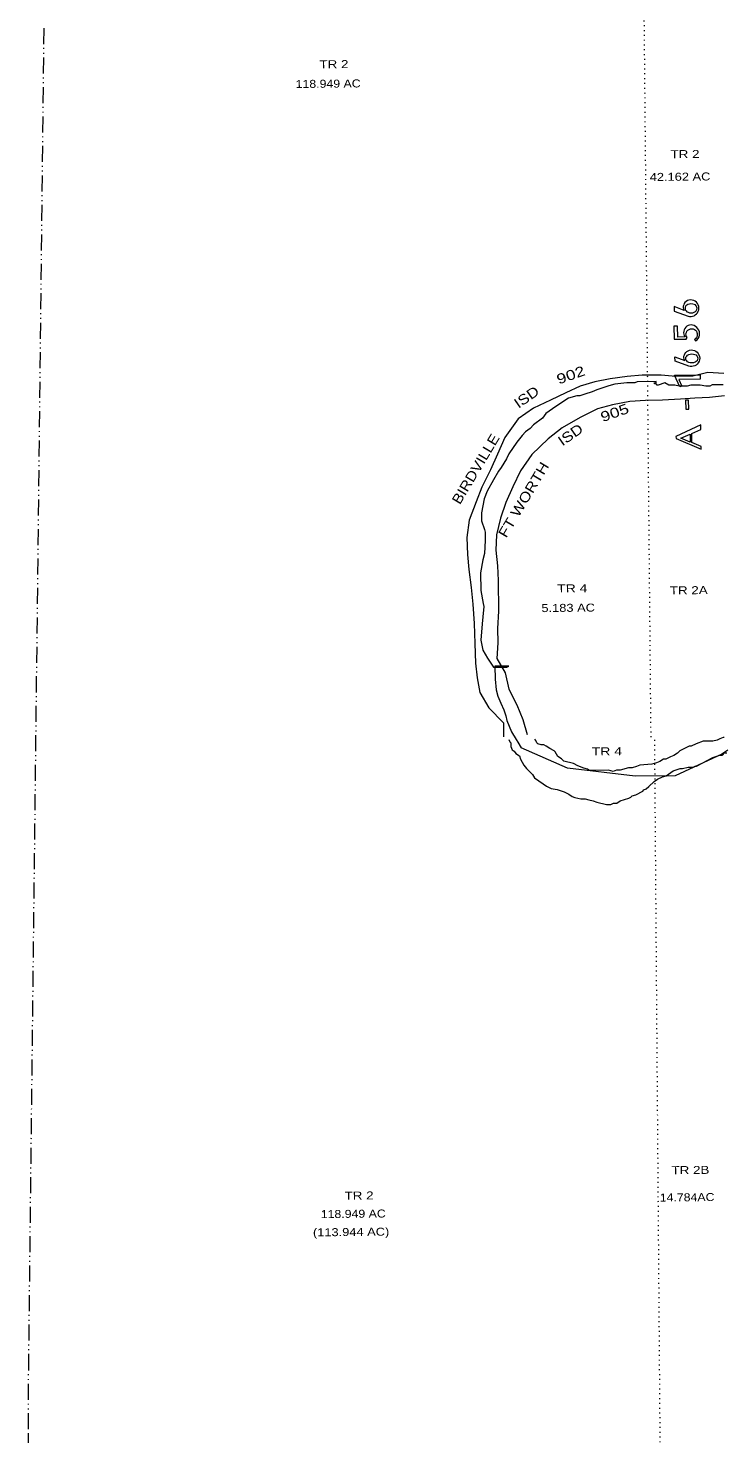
# Model space of a CAD drawing. Extents: x 2356373 to 2371954, y 6966197 to 6989612.
# Drawn here: x 2364597 to 2365996, y 6971494 to 6974303 of the extents above; entities that cross this region are included whole.
import ezdxf

# ---------------------------------------------------------------- set-up
doc = ezdxf.new("R2010")
doc.units = 0
doc.header["$LTSCALE"] = 6.4
doc.linetypes.add('DASH_DOUBLE_DOT', pattern=[9.2, 5, -1.2, 0.3, -1.2, 0.3, -1.2])
doc.linetypes.add('DOTTED', pattern=[1.5, 0.3, -1.2])
for name, color, linetype in [('10', 7, 'Continuous'), ('11', 7, 'Continuous'), ('21', 7, 'Continuous')]:
    doc.layers.add(name, color=color, linetype=linetype)
for name, color, linetype, lineweight in [('15', 7, 'Continuous', 13), ('17', 7, 'Continuous', 13), ('23', 7, 'Continuous', 13), ('4', 7, 'Continuous', 13), ('8', 7, 'Continuous', 13)]:
    doc.layers.add(name, color=color, linetype=linetype, lineweight=lineweight)

msp = doc.modelspace()

# ---------------------------------------------------------------- linework, layer by layer
at = {"layer": '15', "linetype": 'DASH_DOUBLE_DOT'}
for p, q in [((2364628.393, 6974302.6), (2364597.776, 6971649.065)), ((2364597.054, 6971494.488), (2364600.459, 6969921.411))]:
    msp.add_line(p, q, dxfattribs=at)
msp.add_arc((2376052.57, 6971519.304), 11455.546, 179.33414, 180.12414, dxfattribs=at)
at = {"layer": '17'}
for points in [[(2365915.956, 6973727.13), (2365918.962, 6973726.511), (2365921.962, 6973726.391), (2365924.957, 6973726.87), (2365927.947, 6973727.85), (2365930.43, 6973729.373), (2365932.911, 6973731.347), (2365934.886, 6973733.866), (2365936.357, 6973736.778), (2365937.324, 6973739.888), (2365937.793, 6973743.14), (2365937.262, 6973746.386), (2365936.23, 6973749.474), (2365934.703, 6973752.358), (2365932.68, 6973754.839), (2365930.161, 6973756.813), (2365927.148, 6973758.283), (2365924.14, 6973759.153), (2365921.138, 6973759.424), (2365917.642, 6973759.04), (2365914.654, 6973758.01), (2365912.169, 6973756.436), (2365909.692, 6973754.313), (2365908.214, 6973751.998), (2365907.241, 6973749.439), (2365906.267, 6973746.731), (2365906.294, 6973743.932), (2365906.822, 6973741.138), (2365907.846, 6973738.548), (2365888.278, 6973746.005), (2365888.364, 6973737.308), (2365915.956, 6973727.13)], [(2365915.883, 6973734.679), (2365918.889, 6973733.909), (2365922.391, 6973733.693), (2365925.387, 6973733.972), (2365928.378, 6973734.801), (2365930.864, 6973736.076), (2365932.345, 6973737.939), (2365933.323, 6973740.248), (2365933.798, 6973742.802), (2365933.273, 6973745.295), (2365932.252, 6973747.536), (2365930.734, 6973749.37), (2365928.223, 6973750.595), (2365925.216, 6973751.316), (2365921.716, 6973751.531), (2365918.718, 6973751.203), (2365915.228, 6973750.468), (2365913.24, 6973749.199), (2365911.759, 6973747.335), (2365910.282, 6973745.021), (2365910.307, 6973742.471), (2365910.332, 6973739.972), (2365911.854, 6973737.688), (2365913.371, 6973735.852), (2365915.883, 6973734.679)], [(2365930.73, 6973698.934), (2365932.747, 6973696.953), (2365933.772, 6973694.615), (2365934.295, 6973692.121), (2365934.32, 6973689.472), (2365933.847, 6973686.918), (2365932.87, 6973684.559), (2365931.39, 6973682.495), (2365929.408, 6973680.826), (2365930.938, 6973677.641), (2365933.917, 6973679.82), (2365935.89, 6973682.438), (2365937.86, 6973685.507), (2365938.826, 6973688.816), (2365938.794, 6973692.265), (2365938.76, 6973695.714), (2365937.728, 6973698.951), (2365935.699, 6973701.982), (2365933.673, 6973704.562), (2365930.655, 6973706.631), (2365928.139, 6973708.156), (2365925.131, 6973709.076), (2365922.128, 6973709.446), (2365919.132, 6973709.167), (2365916.14, 6973708.339), (2365913.656, 6973706.914), (2365911.175, 6973704.94), (2365909.199, 6973702.62), (2365908.227, 6973699.912), (2365907.255, 6973697.004), (2365906.784, 6973693.95), (2365907.314, 6973690.956), (2365908.342, 6973688.067), (2365909.867, 6973685.483), (2365895.373, 6973685.24), (2365895.155, 6973707.331), (2365887.659, 6973707.208), (2365888.419, 6973680.772), (2365912.409, 6973681.159), (2365913.88, 6973684.122), (2365912.856, 6973686.562), (2365911.831, 6973689.202), (2365911.804, 6973691.949), (2365912.777, 6973694.609), (2365913.754, 6973697.018), (2365915.732, 6973699.036), (2365918.216, 6973700.561), (2365920.707, 6973701.535), (2365923.202, 6973701.858), (2365926.206, 6973701.489), (2365928.715, 6973700.513), (2365930.73, 6973698.934)], [(2365931.643, 6973656.854), (2365934.162, 6973654.88), (2365936.186, 6973652.4), (2365937.713, 6973649.515), (2365938.743, 6973646.426), (2365939.276, 6973643.182), (2365938.807, 6973639.929), (2365937.838, 6973636.82), (2365936.367, 6973633.907), (2365934.392, 6973631.388), (2365931.913, 6973629.415), (2365929.428, 6973627.89), (2365926.438, 6973626.911), (2365923.445, 6973626.432), (2365920.444, 6973626.552), (2365917.438, 6973627.223), (2365889.846, 6973637.349), (2365889.76, 6973646.046), (2365909.329, 6973638.59), (2365908.303, 6973641.178), (2365907.776, 6973643.973), (2365907.748, 6973646.772), (2365908.721, 6973649.481), (2365909.696, 6973652.039), (2365911.173, 6973654.354), (2365913.651, 6973656.477), (2365916.135, 6973658.05), (2365919.125, 6973659.08), (2365922.62, 6973659.465), (2365925.622, 6973659.194), (2365928.63, 6973658.324), (2365931.643, 6973656.854)], [(2365926.699, 6973651.357), (2365929.705, 6973650.636), (2365932.215, 6973649.411), (2365933.732, 6973647.577), (2365934.755, 6973645.336), (2365935.279, 6973642.843), (2365934.805, 6973640.288), (2365933.828, 6973637.982), (2365932.346, 6973636.117), (2365929.86, 6973634.842), (2365926.869, 6973634.013), (2365923.872, 6973633.734), (2365920.371, 6973633.949), (2365917.364, 6973634.719), (2365914.854, 6973635.895), (2365913.336, 6973637.73), (2365911.813, 6973640.013), (2365911.79, 6973642.513), (2365911.763, 6973645.061), (2365913.241, 6973647.376), (2365914.723, 6973649.24), (2365917.209, 6973650.514), (2365920.201, 6973651.243), (2365923.196, 6973651.572), (2365926.699, 6973651.357)], [(2365889.125, 6973608.949), (2365940.103, 6973609.749), (2365940.189, 6973601.002), (2365897.208, 6973600.331), (2365903.332, 6973587.444), (2365899.35, 6973585.756), (2365889.125, 6973608.949)], [(2365917.284, 6973540.994), (2365917.105, 6973559.386), (2365911.107, 6973559.328), (2365911.787, 6973540.941), (2365917.284, 6973540.994)], [(2365923.259, 6973492.565), (2365941.675, 6973500.593), (2365941.585, 6973509.79), (2365891.828, 6973486.508), (2365891.862, 6973482.86), (2365942.065, 6973460.908), (2365942.007, 6973466.856), (2365923.438, 6973474.321), (2365923.259, 6973492.565)], [(2365901.359, 6973483.102), (2365920.272, 6973491.337), (2365920.428, 6973475.491), (2365901.359, 6973483.102)]]:
    msp.add_lwpolyline(points, close=True, dxfattribs=at)
msp.add_lwpolyline([(2365929.408, 6973680.826), (2365930.938, 6973677.641), (2365929.408, 6973680.826)], dxfattribs=at)
at = {"layer": '23'}
for points in [[(2365986.36, 6973589.609), (2365964.367, 6973589.493), (2365959.39, 6973587.146), (2365951.392, 6973587.166), (2365940.373, 6973589.458), (2365921.379, 6973589.372), (2365914.404, 6973587.003), (2365898.408, 6973586.946), (2365889.387, 6973589.358), (2365877.391, 6973589.239), (2365869.351, 6973593.56), (2365856.398, 6973589.233), (2365854.398, 6973589.212), (2365852.375, 6973591.592), (2365849.377, 6973591.562), (2365847.354, 6973593.843), (2365852.352, 6973593.892), (2365852.329, 6973596.192), (2365814.34, 6973596.118), (2365809.365, 6973593.771), (2365793.37, 6973593.712), (2365769.403, 6973590.978), (2365757.437, 6973587.961), (2365733.52, 6973580.028), (2365724.567, 6973575.542), (2365709.614, 6973571.295), (2365699.65, 6973567.698), (2365693.653, 6973567.639), (2365676.698, 6973563.475), (2365651.87, 6973546.735), (2365632.013, 6973532.543), (2365625.111, 6973522.879), (2365607.243, 6973509.806), (2365600.315, 6973502.839), (2365591.387, 6973495.753), (2365584.457, 6973488.788), (2365573.592, 6973475.185), (2365557.826, 6973451.836), (2365552.924, 6973442.09), (2365542.097, 6973424.69), (2365537.173, 6973417.142), (2365527.345, 6973399.85), (2365514.572, 6973377.231), (2365508.724, 6973361.877), (2365503.001, 6973333.829), (2365503.157, 6973317.934), (2365509.324, 6973300.899), (2365510.374, 6973295.511), (2365510.542, 6973278.518), (2365508.797, 6973252.508), (2365505.923, 6973239.783), (2365501.175, 6973214.342), (2365501.523, 6973178.956), (2365506.781, 6973152.514), (2365507.837, 6973146.726), (2365506.042, 6973126.014), (2365504.181, 6973111.899), (2365501.503, 6973079.281), (2365505.692, 6973059.828), (2365514.846, 6973043.922), (2365527.026, 6973025.347), (2365554.018, 6973025.412), (2365557.994, 6973027.75), (2365530.002, 6973027.676), (2365530.255, 6973001.885), (2365532.468, 6972980.113), (2365535.59, 6972967.647), (2365541.728, 6972953.411), (2365547.858, 6972940.074), (2365551.97, 6972928.618), (2365554.066, 6972918.741), (2365563.283, 6972896.437), (2365572.43, 6972881.131)], [(2365572.43, 6972881.131), (2365575.483, 6972875.764), (2365582.593, 6972864.236)], [(2365995.528, 6972859.695), (2365983.606, 6972852.079), (2365890.056, 6972808.672), (2365810.086, 6972807.887), (2365674.968, 6972823.554), (2365582.593, 6972864.236)]]:
    msp.add_lwpolyline(points, dxfattribs=at)
at = {"layer": '4', "linetype": 'DOTTED'}
for p, q in [((2365818.818, 6975277.812), (2365841.332, 6972883.773)), ((2365872.051, 6969959.954), (2365849.329, 6972883.852))]:
    msp.add_line(p, q, dxfattribs=at)
at = {"layer": '8'}
for points in [[(2365987.133, 6973612.61), (2365955.12, 6973614.697), (2365925.2, 6973607.404), (2365891.222, 6973606.17), (2365862.199, 6973609.184), (2365824.212, 6973608.911), (2365794.246, 6973606.318), (2365760.299, 6973601.885), (2365729.363, 6973596.083), (2365700.46, 6973587.101), (2365671.597, 6973573.921), (2365640.748, 6973559.323), (2365606.919, 6973542.994), (2365576.134, 6973521.896), (2365549.51, 6973484.245), (2365534.838, 6973451.31), (2365521.147, 6973420.185), (2365503.493, 6973385.52), (2365492.787, 6973355.822), (2365478.147, 6973319.689), (2365473.493, 6973284.553), (2365474.824, 6973250.874), (2365478.118, 6973220.814), (2365482.471, 6973184.867), (2365485.799, 6973151.209), (2365488.177, 6973112.841), (2365489.569, 6973072.768), (2365490.951, 6973033.891), (2365494.241, 6973004.33), (2365499.53, 6972974.79), (2365517.822, 6972944.478), (2365547.109, 6972914.375), (2365547.387, 6972886.184)], [(2365988.572, 6973567.838), (2365958.615, 6973564.344), (2365929.633, 6973563.26), (2365900.658, 6973561.475), (2365864.688, 6973559.422), (2365830.705, 6973558.587), (2365799.733, 6973556.585), (2365764.808, 6973549.844), (2365734.898, 6973541.652), (2365700.073, 6973524.714), (2365664.29, 6973503.669), (2365636.512, 6973481.702), (2365603.829, 6973450.388), (2365581.152, 6973418.074), (2365565.472, 6973386.029), (2365551.781, 6973354.903), (2365541.091, 6973323.505), (2365533.426, 6973289.739), (2365531.721, 6973259.632), (2365535.03, 6973228.272), (2365536.32, 6973198.693), (2365536.923, 6973137.315), (2365535.262, 6973102.708), (2365535.545, 6973074.019), (2365533.85, 6973043.01), (2365550.129, 6973014.178), (2365557.449, 6972981.457), (2365573.747, 6972950.527), (2365586.033, 6972921.055), (2365594.329, 6972890.744)], [(2365988.279, 6972885.218), (2365988.283, 6972884.916), (2365986.283, 6972884.897), (2365979.309, 6972882.428), (2365974.333, 6972880.079), (2365965.359, 6972877.693), (2365946.366, 6972877.507), (2365932.417, 6972872.671), (2365922.467, 6972867.874), (2365918.467, 6972867.835), (2365899.567, 6972858.352), (2365894.615, 6972853.604), (2365887.663, 6972848.837), (2365880.688, 6972846.469), (2365871.737, 6972841.683), (2365866.74, 6972841.633), (2365859.789, 6972836.867), (2365852.813, 6972834.499), (2365843.84, 6972832.012), (2365819.872, 6972829.476), (2365812.896, 6972827.108), (2365803.924, 6972824.622), (2365796.926, 6972824.553), (2365779.978, 6972819.788), (2365772.98, 6972819.719), (2365766.006, 6972817.25), (2365756.985, 6972819.562), (2365718.999, 6972819.289), (2365714.978, 6972821.548), (2365707.956, 6972823.879), (2365695.915, 6972828.459), (2365686.872, 6972833.069), (2365667.832, 6972837.58), (2365662.789, 6972842.23), (2365655.743, 6972846.96), (2365650.652, 6972856.306), (2365648.631, 6972858.586), (2365639.589, 6972863.196), (2365632.544, 6972867.826), (2365627.522, 6972870.175), (2365622.525, 6972870.128), (2365615.504, 6972872.459), (2365613.482, 6972874.736), (2365611.436, 6972879.416), (2365609.417, 6972881.494)], [(2365988.279, 6972885.218), (2365988.283, 6972884.916), (2365988.279, 6972885.218)], [(2365557.435, 6972880.985), (2365559.477, 6972876.607), (2365561.5, 6972874.326), (2365561.569, 6972867.229), (2365564.638, 6972860.261), (2365568.659, 6972857.9), (2365571.704, 6972853.232), (2365578.747, 6972848.602), (2365580.816, 6972841.624), (2365587.929, 6972829.898), (2365592.996, 6972822.949), (2365605.108, 6972811.272), (2365609.176, 6972804.213), (2365626.285, 6972792.684), (2365633.328, 6972788.055), (2365642.372, 6972783.445), (2365654.391, 6972781.164), (2365668.432, 6972776.603), (2365677.475, 6972771.994), (2365684.519, 6972767.263), (2365689.54, 6972765.013), (2365701.558, 6972762.731), (2365710.556, 6972762.82), (2365717.576, 6972760.591), (2365726.596, 6972758.28), (2365733.617, 6972755.949), (2365752.656, 6972751.437), (2365761.653, 6972751.525), (2365766.628, 6972753.873), (2365773.626, 6972753.943), (2365780.577, 6972758.709), (2365797.526, 6972763.574), (2365801.501, 6972765.914), (2365804.477, 6972768.342), (2365811.451, 6972770.71), (2365825.378, 6972777.844), (2365827.353, 6972780.263), (2365832.329, 6972782.612), (2365837.281, 6972787.359), (2365848.184, 6972796.863), (2365855.136, 6972801.63), (2365865.088, 6972806.328), (2365872.06, 6972808.794), (2365885.964, 6972818.329), (2365899.913, 6972823.065), (2365904.912, 6972823.114), (2365915.884, 6972825.621), (2365925.881, 6972825.62), (2365929.856, 6972828.057), (2365932.855, 6972828.087), (2365965.682, 6972844.805), (2365979.632, 6972849.541), (2365983.631, 6972849.581), (2365986.606, 6972852.009), (2365986.583, 6972854.309), (2365993.581, 6972854.376)]]:
    msp.add_lwpolyline(points, dxfattribs=at)

# ---------------------------------------------------------------- texts
at = {"layer": '10'}
for s, width, p in [('TR 2', 1.25, (2365179.359, 6974222.212)), ('TR 2', 1.25, (2365880.937, 6974042.554)), ('TR 4', 1.3, (2365654.522, 6973174.86)), ('TR 2A', 1.25, (2365879.5, 6973170.972)), ('TR 4', 1.3, (2365723.703, 6972849.226)), ('TR 2B', 1.25, (2365882.883, 6972012.413)), ('TR 2', 1.25, (2365229.557, 6971961.509))]:
    msp.add_text(s, height=15.99, rotation=0.563, dxfattribs=dict(at, width=width)).set_placement(p)
at = {"layer": '11'}
for s, width, p in [('118.949 AC', 1.15, (2365131.759, 6974182.856)), ('42.162 AC', 1.2, (2365839.394, 6973997.057)), ('5.183 AC', 1.2, (2365622.916, 6973135.661)), ('14.784AC', 1.15, (2365859.425, 6971957.798)), ('118.949 AC', 1.15, (2365181.933, 6971924.65)), ('(113.944 AC)', 1.2, (2365166.294, 6971888.207))]:
    msp.add_text(s, height=15.99, rotation=0.563, dxfattribs=dict(at, width=width)).set_placement(p)
at = {"layer": '21'}
for s, rotation, width, p in [('902', 19.431, 1.3, (2365657.439, 6973590.378)), ('ISD', 34.917, 1.2, (2365576.938, 6973541.801)), ('905', 19.431, 1.3, (2365745.156, 6973515.06)), ('ISD', 34.917, 1.2, (2365664.654, 6973466.58)), ('BIRDVILLE', 59.197, 1.15, (2365459.862, 6973349.101)), ('FT WORTH', 59.197, 1.2, (2365552.493, 6973282.429))]:
    msp.add_text(s, height=19.99, rotation=rotation, dxfattribs=dict(at, width=width)).set_placement(p)

doc.saveas('drawing.dxf')
